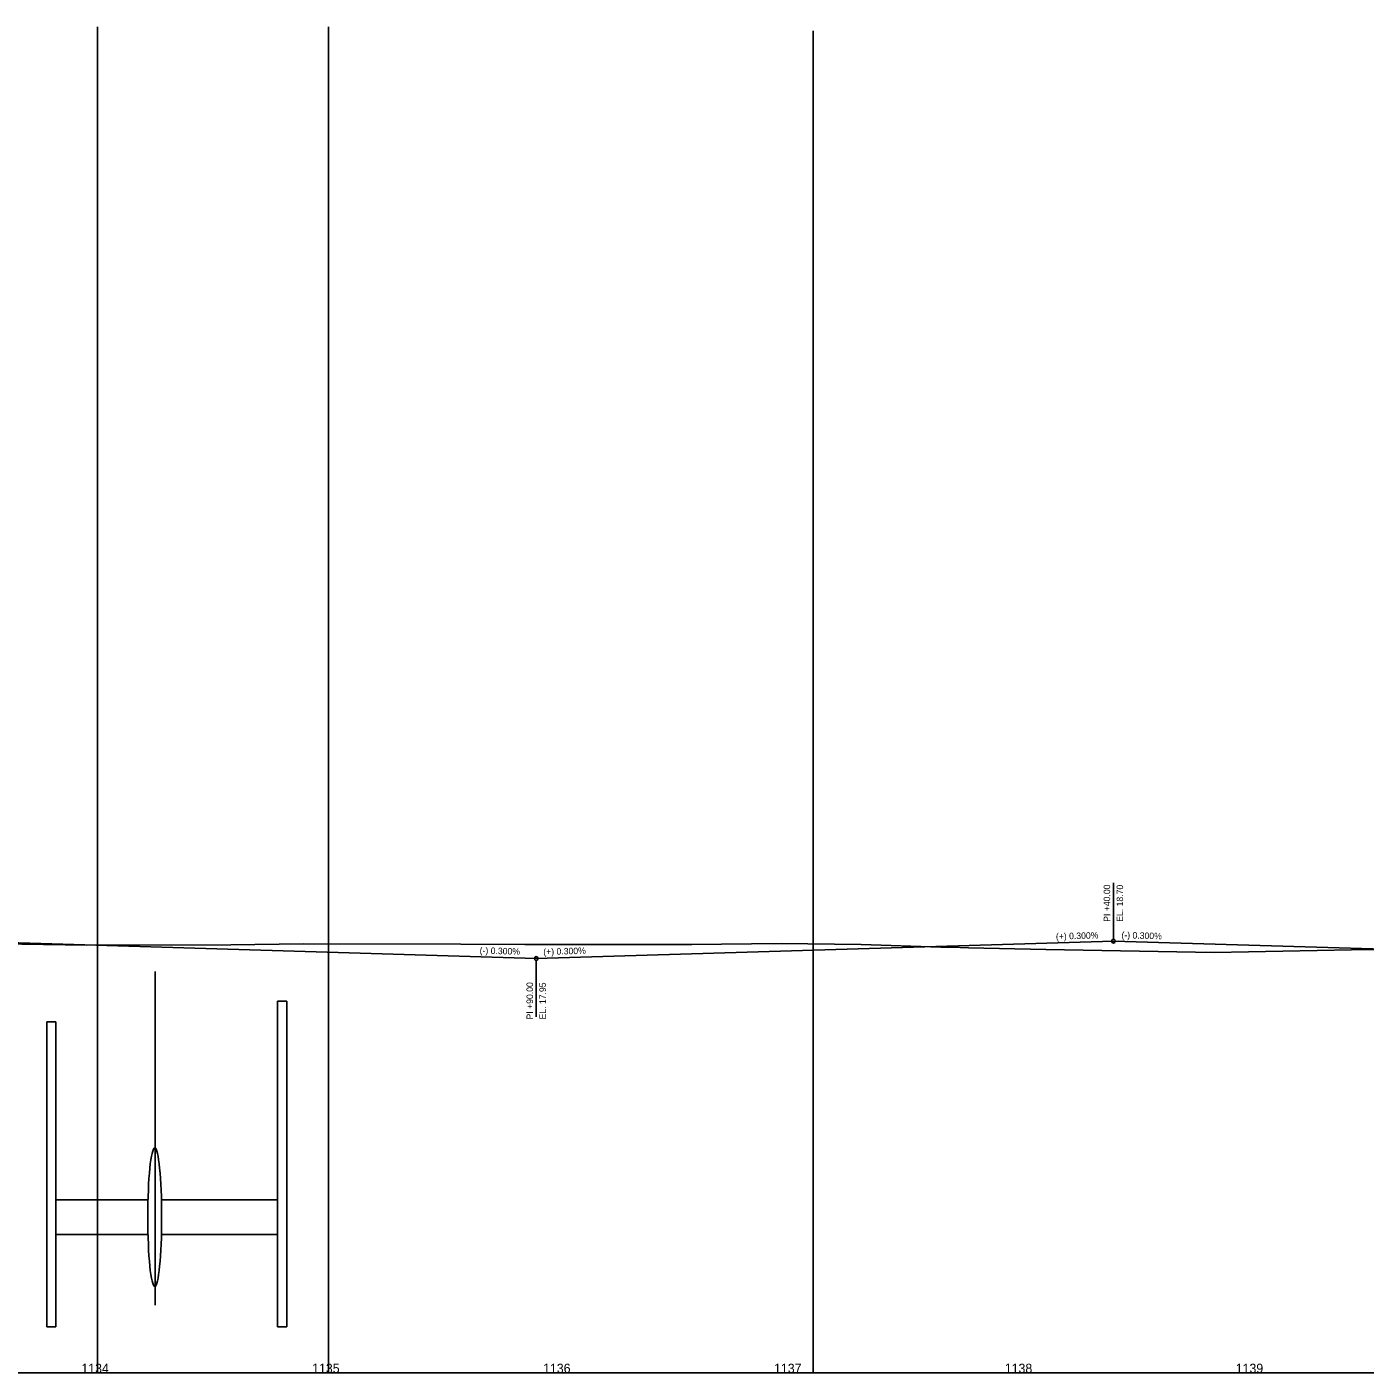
# Model space of a CAD drawing. Extents: x 1409 to 6106, y -2180 to -1584.
# Drawn here: x 3180 to 3760, y -2180 to -1597 of the extents above; entities that cross this region are included whole.
import ezdxf

# ---------------------------------------------------------------- set-up
doc = ezdxf.new("R2010")
doc.units = 0
for name, color, linetype in [('CLConst_dp', 7, 'Continuous'), ('DrainStruct_pr', 7, 'Continuous'), ('LaneLine', 7, 'Continuous'), ('Miscellaneous0', 7, 'Continuous'), ('NonPlottingEle_dp', 7, 'Continuous'), ('PipeCulvert_ep', 7, 'Continuous'), ('PipeCulvert_pr', 7, 'Continuous'), ('StationTicS_dp', 7, 'Continuous'), ('TextLabel', 7, 'Continuous'), ('TextProfLabel', 7, 'Continuous'), ('TextPtLabel', 7, 'Continuous')]:
    doc.layers.add(name, color=color, linetype=linetype)

msp = doc.modelspace()

# ---------------------------------------------------------------- linework, layer by layer
at = {"layer": 'CLConst_dp'}
msp.add_line((1410.73, -2179.71), (6032.47, -2179.71), dxfattribs=at)
at = {"layer": 'DrainStruct_pr'}
for p, q in [((3288.73, -2018.71), (3288.73, -2159.71)), ((3292.73, -2018.71), (3292.73, -2159.71)), ((3188.73, -2027.71), (3192.73, -2027.71)), ((3188.73, -2027.71), (3188.73, -2159.71)), ((3192.73, -2027.71), (3192.73, -2159.71)), ((3188.73, -2159.71), (3192.73, -2159.71))]:
    msp.add_line(p, q, dxfattribs=at)
at = {"layer": 'Miscellaneous0'}
for p, q in [((3210.73, -2179.71), (3210.73, -1596.74)), ((3310.73, -2179.71), (3310.73, -1596.74))]:
    msp.add_line(p, q, dxfattribs=at)
at = {"layer": 'NonPlottingEle_dp'}
for p, q in [((3650.73, -1991.91), (3650.73, -1967.51)), ((3400.73, -2001.01), (3400.73, -2025.41))]:
    msp.add_line(p, q, dxfattribs=at)
for centre in [(3650.73, -1992.71), (3400.73, -2000.21)]:
    msp.add_circle(centre, 0.8, dxfattribs=at)
at = {"layer": 'PipeCulvert_ep'}
msp.add_ellipse((3235.51, -2112.24), major_axis=(0, 30), ratio=0.1, dxfattribs=at)
at = {"layer": 'PipeCulvert_pr'}
for p, q in [((3288.73, -2018.71), (3292.73, -2018.71)), ((3192.73, -2104.71), (3232.6, -2104.71)), ((3238.41, -2104.71), (3288.73, -2104.71)), ((3192.73, -2119.71), (3232.6, -2119.71)), ((3238.41, -2119.71), (3288.73, -2119.71)), ((3288.73, -2159.71), (3292.73, -2159.71))]:
    msp.add_line(p, q, dxfattribs=at)
at = {"layer": 'StationTicS_dp'}
msp.add_lwpolyline([(3168.35, -1993.8), (3206.04, -1994.48), (3268.42, -1994.32), (3299.87, -1993.9), (3368.13, -1994.02), (3395.85, -1994.1), (3468.18, -1994.16), (3506.82, -1993.65), (3541.42, -1994.15), (3576.03, -1995.34), (3584.42, -1995.4), (3588, -1995.54), (3621.44, -1996.35), (3694.38, -1997.66), (3753.84, -1996.48), (3793.77, -1996.12)], dxfattribs=at)
msp.add_lwpolyline([(3168.35, -1993.8), (3206.04, -1994.48), (3268.42, -1994.32), (3299.87, -1993.9), (3368.13, -1994.02), (3395.85, -1994.1), (3468.18, -1994.16), (3506.82, -1993.65), (3541.42, -1994.15), (3576.03, -1995.34), (3584.42, -1995.4), (3588, -1995.54), (3621.44, -1996.35), (3694.38, -1997.66), (3753.84, -1996.48), (3793.77, -1996.12)], dxfattribs=at)
at = {"layer": 'TextLabel'}
for p, q in [((3520.73, -2179.71), (3520.73, -1598.37)), ((3235.73, -2150.41), (3235.73, -2005.87))]:
    msp.add_line(p, q, dxfattribs=at)
at = {"layer": 'TextPtLabel'}
for p, q in [((3150.73, -1992.71), (3400.73, -2000.21)), ((3400.73, -2000.21), (3650.73, -1992.71)), ((3650.73, -1992.71), (3900.73, -2000.21))]:
    msp.add_line(p, q, dxfattribs=at)

# ---------------------------------------------------------------- texts
at = {"layer": 'LaneLine'}
for s, rotation, p in [('(+) 0.300%', 1.71836, (3625.86, -1992.06)), ('(-) 0.300%', 358.28164, (3654.2, -1991.42)), ('(-) 0.300%', 358.28164, (3376.21, -1998.08)), ('(+) 0.300%', 1.71836, (3403.85, -1998.72))]:
    msp.add_text(s, height=2.8, rotation=rotation, dxfattribs=at).set_placement(p)
at = {"layer": 'NonPlottingEle_dp'}
for s, p in [('PI +40.00', (3649.33, -1984.31)), ('EL. 18.70', (3654.93, -1984.31)), ('PI +90.00', (3399.33, -2026.61)), ('EL. 17.95', (3404.93, -2026.61))]:
    msp.add_text(s, height=2.8, rotation=90, dxfattribs=at).set_placement(p)
at = {"layer": 'TextProfLabel'}
for s, p in [('1134', (3203.74, -2179.71)), ('1135', (3303.68, -2179.71)), ('1136', (3403.71, -2179.71)), ('1137', (3503.75, -2179.71)), ('1138', (3603.68, -2179.71)), ('1139', (3703.71, -2179.71))]:
    msp.add_text(s, height=4, dxfattribs=at).set_placement(p)

doc.saveas('drawing.dxf')
